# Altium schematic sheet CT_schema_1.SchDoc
size 407 x 198 mm
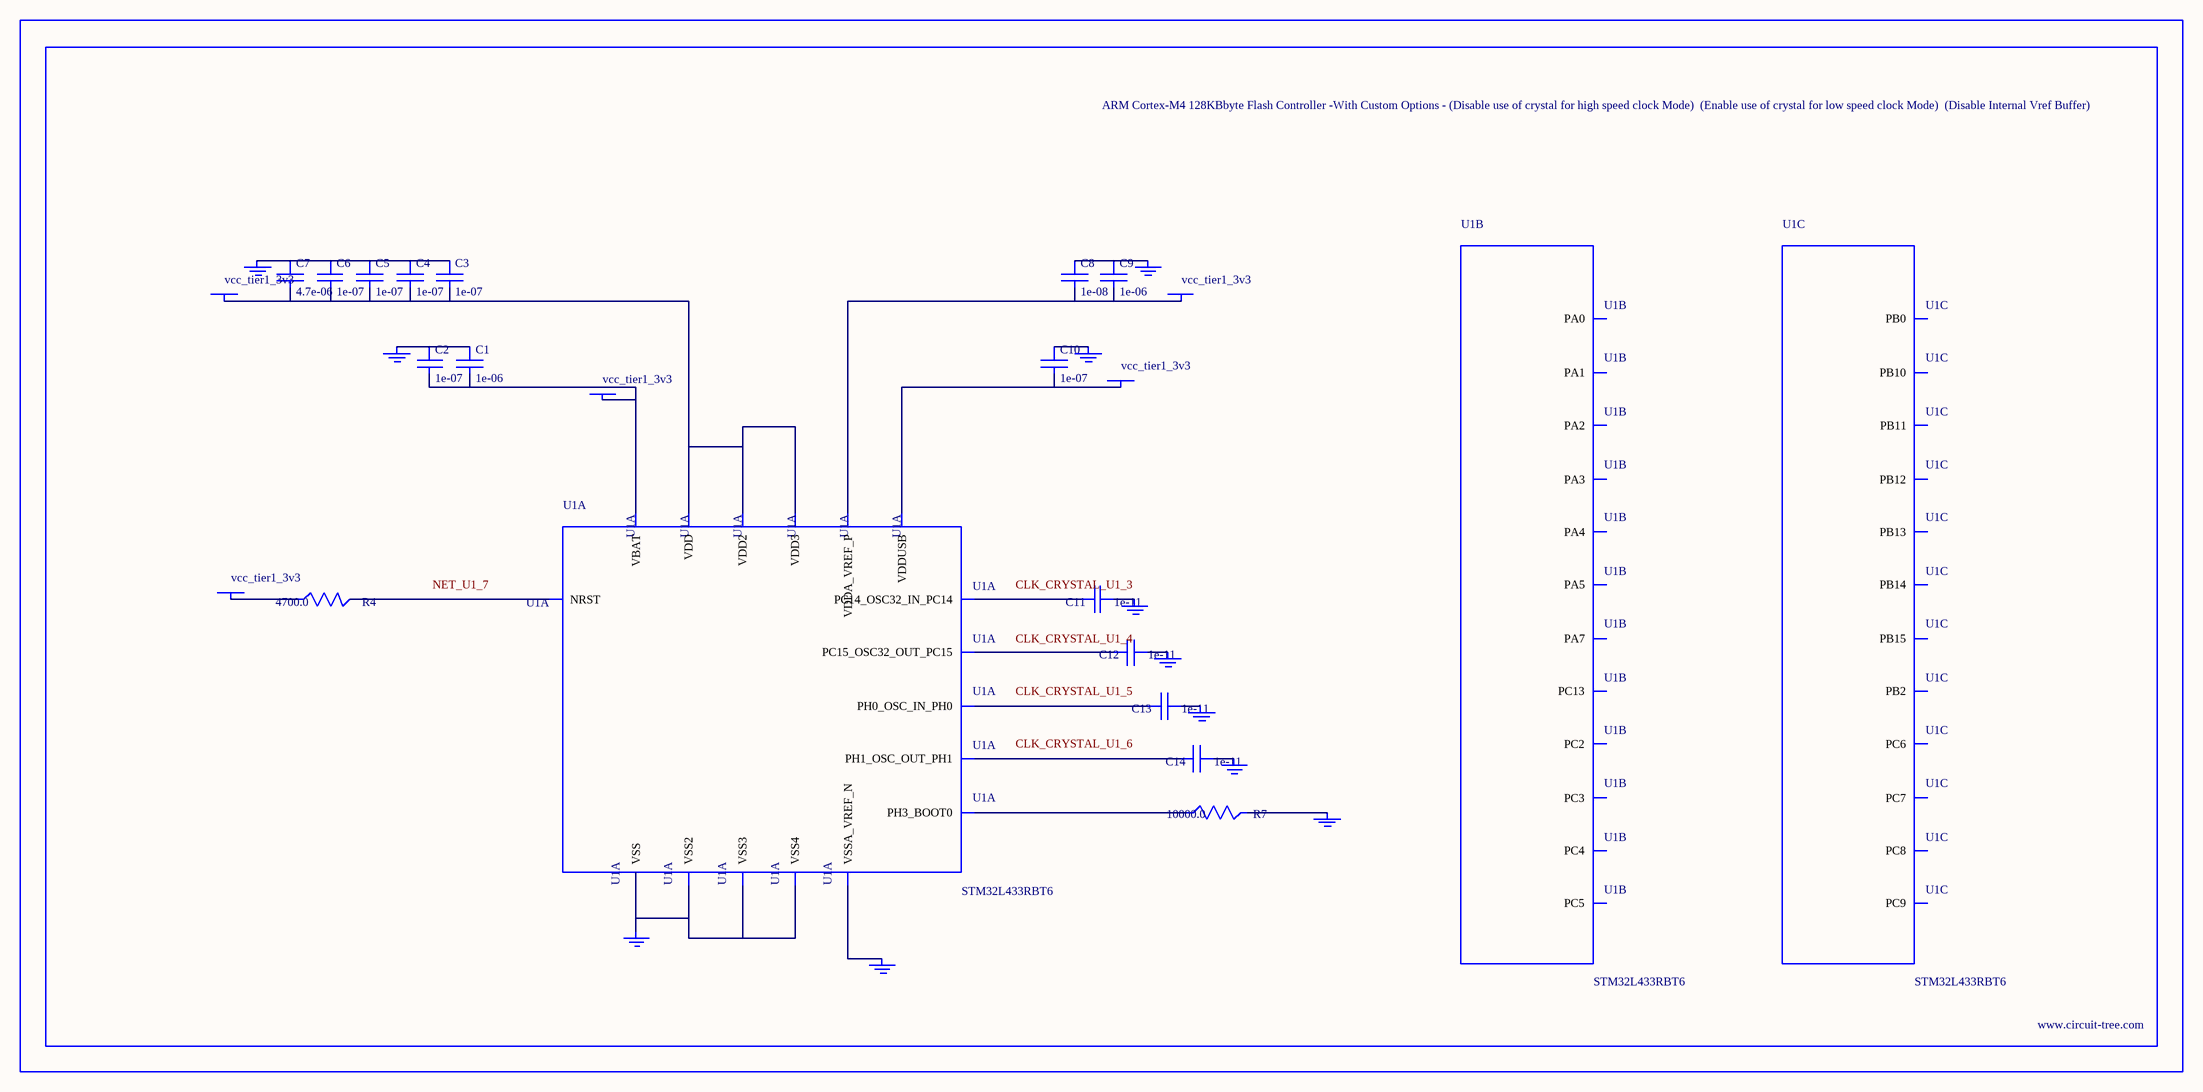
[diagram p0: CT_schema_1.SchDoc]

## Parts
BORDER0  (no value)
C1  1e-06  [C0603]
C2  1e-07  [C0603]
C3  1e-07  [C0603]
C4  1e-07  [C0603]
C5  1e-07  [C0603]
C6  1e-07  [C0603]
C7  4.7e-06  [C0603]
C8  1e-08  [C0603]
C9  1e-06  [C0603]
C10  1e-07  [C0603]
C11  1e-11  [C0402]
C12  1e-11  [C0402]
C13  1e-11  [C0402]
C14  1e-11  [C0402]
GND_INSTANCE_0_0  (no value)
GND_INSTANCE_0_1  (no value)
GND_INSTANCE_0_2  (no value)
GND_INSTANCE_0_3  (no value)
GND_INSTANCE_0_4  (no value)
GND_INSTANCE_0_5  (no value)
GND_INSTANCE_0_6  (no value)
GND_INSTANCE_0_7  (no value)
GND_INSTANCE_0_8  (no value)
GND_INSTANCE_0_9  (no value)
GND_INSTANCE_0_10  (no value)
POWER_INSTANCE_0_0  vcc_tier1_3v3
POWER_INSTANCE_0_1  vcc_tier1_3v3
POWER_INSTANCE_0_2  vcc_tier1_3v3
POWER_INSTANCE_0_3  vcc_tier1_3v3
POWER_INSTANCE_0_4  vcc_tier1_3v3
R4  4700.0  [R0603]
R7  10000.0  [R0603]
U1  STM32L433RBT6  [LQFP64]  (parts A,B,C of 7)

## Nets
NetC1_1: C1.1 C2.1 GND_INSTANCE_0_0.0(GND)
NetC1_2: C1.2 C2.2 POWER_INSTANCE_0_0.0(PWR) U1.1(VBAT)
NetC3_1: C3.1 C4.1 C5.1 C6.1 C7.1 GND_INSTANCE_0_7.0(GND)
NetC3_2: C3.2 C4.2 C5.2 C6.2 C7.2 POWER_INSTANCE_0_2.0(PWR) U1.19(VDD) U1.32(VDD2) U1.64(VDD3)
NetC8_1: C8.1 C9.1 GND_INSTANCE_0_6.0(GND)
NetC8_2: C8.2 C9.2 POWER_INSTANCE_0_1.0(PWR) U1.13(VDDA_VREF_P)
NetC10_1: C10.1 GND_INSTANCE_0_8.0(GND)
NetC10_2: C10.2 POWER_INSTANCE_0_3.0(PWR) U1.48(VDDUSB)
NetC11_1: C11.1 GND_INSTANCE_0_1.0(GND)
NetC11_2: C11.2 U1.3(PC14_OSC32_IN_PC14)
NetC12_1: C12.1 GND_INSTANCE_0_2.0(GND)
NetC12_2: C12.2 U1.4(PC15_OSC32_OUT_PC15)
NetC13_1: C13.1 GND_INSTANCE_0_3.0(GND)
NetC13_2: C13.2 U1.5(PH0_OSC_IN_PH0)
NetC14_1: C14.1 GND_INSTANCE_0_4.0(GND)
NetC14_2: C14.2 U1.6(PH1_OSC_OUT_PH1)
NetGND_INSTANCE_0_5_0: GND_INSTANCE_0_5.0(GND) U1.12(VSSA_VREF_N)
NetGND_INSTANCE_0_9_0: GND_INSTANCE_0_9.0(GND) R7.2
NetGND_INSTANCE_0_10_0: GND_INSTANCE_0_10.0(GND) U1.18(VSS) U1.31(VSS2) U1.47(VSS3) U1.63(VSS4)
NetPOWER_INSTANCE_0_4_0: POWER_INSTANCE_0_4.0(PWR) R4.1
NetR4_2: R4.2 U1.7(NRST)
NetR7_1: R7.1 U1.60(PH3_BOOT0)

Not connected (* = marked no-connect by the designer): U1 2(PC13) 10(PC2) 11(PC3) 14(PA0) 15(PA1) 16(PA2) 17(PA3) 20(PA4) 21(PA5) 23(PA7) 24(PC4) 25(PC5) 26(PB0) 28(PB2) 29(PB10) 30(PB11) 33(PB12) 34(PB13) 35(PB14) 36(PB15) 37(PC6) 38(PC7) 39(PC8) 40(PC9)

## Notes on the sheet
- Labels drawn without touching a wire or pin: CLK_CRYSTAL_U1_3, CLK_CRYSTAL_U1_4, CLK_CRYSTAL_U1_5, CLK_CRYSTAL_U1_6, NET_U1_7

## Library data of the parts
BORDER0 = BORDER_PAGE0
C1 C9 = C0603C105K3RACTU
C2-C6 C10 = 06035C104K4Z2A
C7 = GRM188R6YA475KE15D
C8 = 06035C103K4Z2A
C11-C14 = C0402C100K3GACTU
GND_INSTANCE_0_0-GND_INSTANCE_0_10 = GND
POWER_INSTANCE_0_0-POWER_INSTANCE_0_4 = PWR
R4 = RC0603JR-074K7L
R7 = RC0603JR-0710KL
